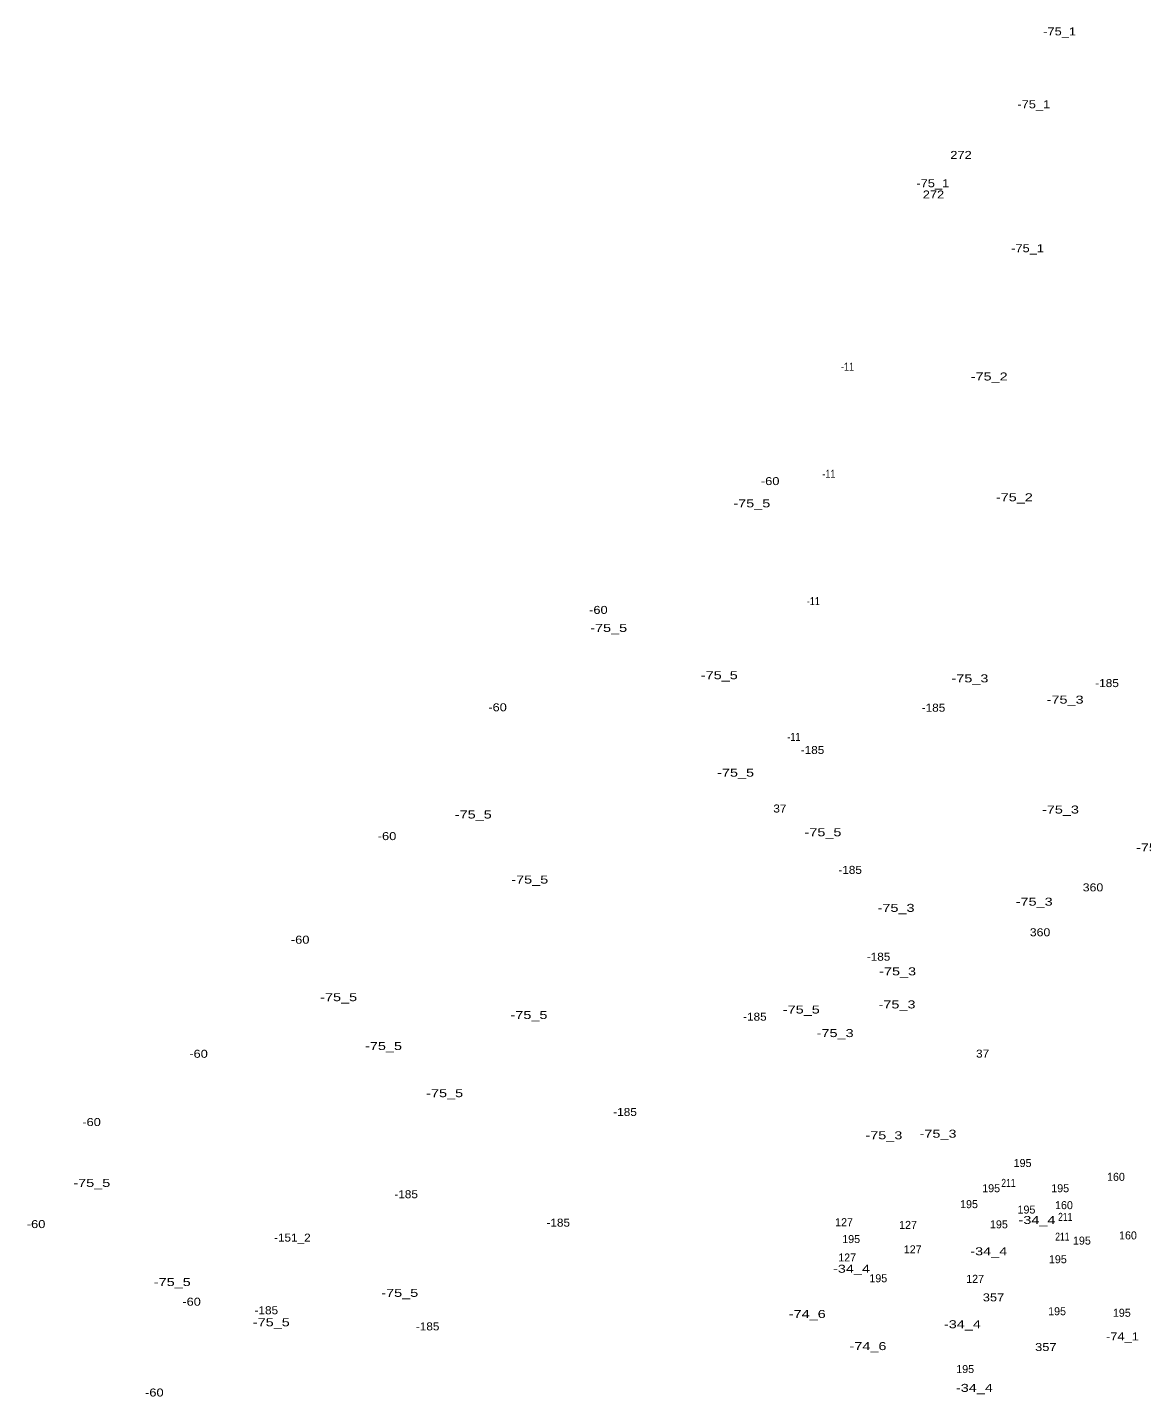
# Model space of a CAD drawing. Extents: x -658110 to -655750, y -1000429 to -997657.
# Drawn here: x -658099 to -657542, y -999109 to -998425 of the extents above; entities that cross this region are included whole.
import ezdxf
from ezdxf.enums import TextEntityAlignment as Align

# ---------------------------------------------------------------- set-up
doc = ezdxf.new("R2010")
doc.units = 0
doc.header["$LTSCALE"] = 1.6
doc.layers.add('24', color=7, linetype='Continuous')

msp = doc.modelspace()

# ---------------------------------------------------------------- texts
at = {"layer": '24'}
for s, width, p in [('-75_1', 1.2, (-657583.26, -998428.8)), ('-75_1', 1.2, (-657596.18, -998465.23)), ('272', 1.2, (-657632.56, -998490.55)), ('-75_1', 1.2, (-657646.66, -998504.7)), ('272', 1.2, (-657646.33, -998510.33)), ('-75_1', 1.2, (-657599.28, -998537.19)), ('-11', 0.85, (-657689.311, -998596.41)), ('-75_2', 1.35, (-657618.47, -998601.3)), ('-60', 1.2, (-657727.96, -998653.58)), ('-11', 0.85, (-657698.62, -998649.94)), ('-75_2', 1.35, (-657605.9, -998661.66)), ('-75_5', 1.35, (-657737.14, -998664.71)), ('-11', 0.85, (-657706.38, -998713.55)), ('-60', 1.2, (-657813.84, -998717.97)), ('-75_5', 1.35, (-657808.7, -998726.98)), ('-75_5', 1.35, (-657753.39, -998750.61)), ('-75_3', 1.35, (-657628.1, -998752.18)), ('-185', 1.1, (-657559.541, -998754.55)), ('-75_3', 1.35, (-657580.51, -998762.81)), ('-60', 1.2, (-657864.25, -998766.64)), ('-185', 1.1, (-657646.321, -998766.85)), ('-11', 0.85, (-657716.071, -998781.43)), ('-185', 1.1, (-657706.801, -998787.98)), ('-75_5', 1.35, (-657745.26, -998799.33)), ('37', 1.1, (-657723.11, -998817.24)), ('-75_3', 1.35, (-657582.83, -998817.76)), ('-75_5', 1.35, (-657876.39, -998820.23)), ('-60', 1.2, (-657919.5, -998831.03)), ('-75_5', 1.35, (-657701.56, -998829.12)), ('-75_3', 1.35, (-657535.83, -998836.72)), ('-75_5', 1.35, (-657848.15, -998852.76)), ('-185', 1.1, (-657687.99, -998847.91)), ('360', 1.15, (-657566.581, -998856.66)), ('-75_3', 1.35, (-657665.03, -998866.9)), ('-75_3', 1.35, (-657595.98, -998863.8)), ('360', 1.15, (-657593.041, -998879.1)), ('-60', 1.2, (-657962.93, -998882.81)), ('-185', 1.1, (-657673.78, -998891.32)), ('-75_3', 1.35, (-657664.25, -998898.63)), ('-75_5', 1.35, (-657943.69, -998911.55)), ('-75_3', 1.35, (-657664.54, -998915.17)), ('-75_5', 1.35, (-657848.54, -998920.45)), ('-185', 1.1, (-657735.611, -998921.29)), ('-75_5', 1.35, (-657712.39, -998917.73)), ('-75_3', 1.35, (-657695.49, -998929.49)), ('-60', 1.2, (-658013.73, -998939.83)), ('-75_5', 1.35, (-657921.26, -998935.95)), ('37', 1.1, (-657621.76, -998939.75)), ('-75_5', 1.35, (-657890.7, -998959.53)), ('-185', 1.1, (-657800.51, -998968.92)), ('-60', 1.2, (-658067.22, -998973.96)), ('-75_3', 1.35, (-657671.12, -998980.57)), ('-75_3', 1.35, (-657644.04, -998979.79)), ('-75_5', 1.35, (-658067.09, -999004.4)), ('-185', 1.1, (-657909.951, -999010.03)), ('211', 0.8, (-657608.84, -999004.38)), ('-185', 1.1, (-657833.921, -999024.24)), ('-34_4', 1.35, (-657594.58, -999022.91)), ('211', 0.8, (-657580.44, -999021.35)), ('-60', 1.2, (-658094.95, -999024.96)), ('-151_2', 1.1, (-657966.84, -999031.72)), ('211', 0.8, (-657581.89, -999031.24)), ('-34_4', 1.35, (-657618.68, -999038.56)), ('-34_4', 1.35, (-657687.31, -999047.29)), ('-75_5', 1.35, (-658026.86, -999053.93)), ('-60', 1.2, (-658017.21, -999063.75)), ('-75_5', 1.35, (-657913.14, -999059.35)), ('357', 1.2, (-657616.31, -999061.58)), ('-185', 1.1, (-657979.841, -999068.03)), ('-74_6', 1.35, (-657709.421, -999069.9)), ('-75_5', 1.35, (-657977.35, -999074.05)), ('-185', 1.1, (-657899.201, -999076.1)), ('-34_4', 1.35, (-657631.86, -999075.02)), ('-74_6', 1.35, (-657679.061, -999085.96)), ('357', 1.2, (-657590.14, -999086.4)), ('-74_1', 1.2, (-657551.84, -999081.1)), ('-34_4', 1.35, (-657625.85, -999106.83)), ('-60', 1.2, (-658035.83, -999109.14))]:
    msp.add_text(s, height=4, dxfattribs=dict(at, width=width)).set_placement(p, align=Align.CENTER)
for s, p in [('195', (-657601.791, -998994.44)), ('160', (-657555.101, -999001.34)), ('195', (-657617.49, -999007.04)), ('195', (-657582.981, -999007.04)), ('195', (-657628.541, -999014.99)), ('195', (-657599.841, -999017.72)), ('160', (-657581.081, -999015.5)), ('127', (-657691.03, -999024.02)), ('127', (-657659.041, -999025.37)), ('195', (-657613.611, -999025.08)), ('160', (-657549.091, -999030.62)), ('195', (-657687.481, -999032.45)), ('127', (-657656.721, -999037.59)), ('195', (-657572.13, -999033.22)), ('127', (-657689.481, -999041.66)), ('195', (-657584.15, -999042.53)), ('195', (-657673.91, -999052.04)), ('127', (-657625.5, -999052.33)), ('195', (-657584.53, -999068.52)), ('195', (-657552.16, -999069.29)), ('195', (-657630.481, -999097.42))]:
    msp.add_text(s, height=4, dxfattribs=at).set_placement(p, align=Align.CENTER)

doc.saveas('drawing.dxf')
